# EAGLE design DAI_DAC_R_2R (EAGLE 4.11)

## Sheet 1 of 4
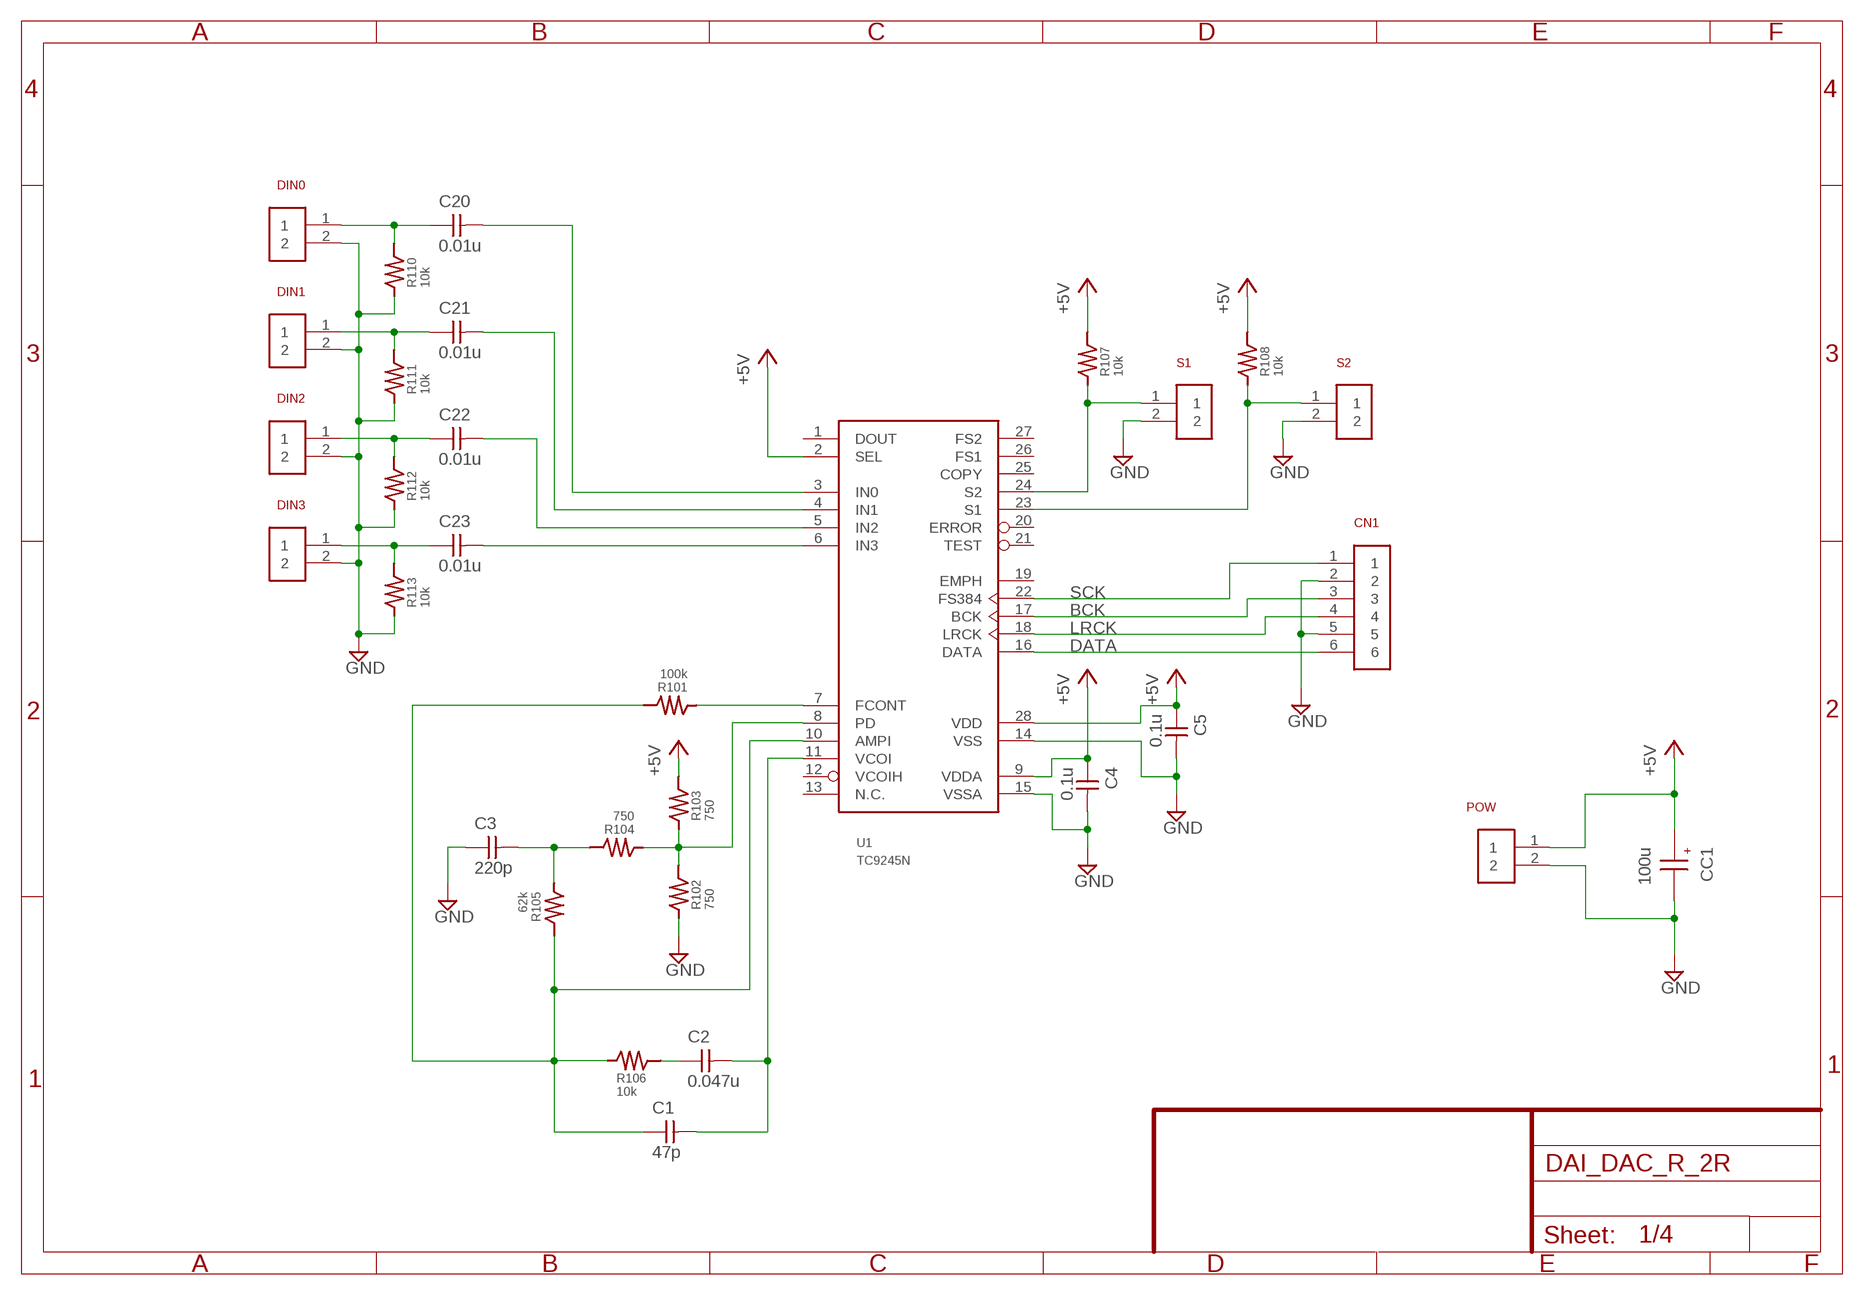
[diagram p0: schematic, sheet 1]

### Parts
C1  47p  CAPNP-5  [C-5]
C2  0.047u  CAPNP-5  [C-5]
C3  220p  CAPNP-5  [C-5]
C4  0.1u  CAPNP-5  [C-5]
C5  0.1u  CAPNP-5  [C-5]
C20  0.01u  CAPNP-5  [C-5]
C21  0.01u  CAPNP-5  [C-5]
C22  0.01u  CAPNP-5  [C-5]
C23  0.01u  CAPNP-5  [C-5]
CC1  100u  CC2.5  [CC2.5]
CN1  PINHEDER_1X6  [PINHEADER_1X6]
DIN0  PINHEADER_1X2  [PINHEADER_1X2]
DIN1  PINHEADER_1X2  [PINHEADER_1X2]
DIN2  PINHEADER_1X2  [PINHEADER_1X2]
DIN3  PINHEADER_1X2  [PINHEADER_1X2]
POW  PINHEADER_1X2  [PINHEADER_1X2]
R101  100k  MINI_R  [MINI_R]
R102  750  MINI_R  [MINI_R]
R103  750  MINI_R  [MINI_R]
R104  750  MINI_R  [MINI_R]
R105  62k  MINI_R  [MINI_R]
R106  10k  MINI_R  [MINI_R]
R107  10k  MINI_R  [MINI_R]
R108  10k  MINI_R  [MINI_R]
R110  10k  MINI_R  [MINI_R]
R111  10k  MINI_R  [MINI_R]
R112  10k  MINI_R  [MINI_R]
R113  10k  MINI_R  [MINI_R]
S1  PINHEADER_1X2  [PINHEADER_1X2]
S2  PINHEADER_1X2  [PINHEADER_1X2]
U1  TC9245N  [TC9245N]

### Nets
+5V: C4.1 C5.1 CC1.P$1 POW.1 R103.P$2(-) R107.P$2(-) R108.P$2(-) U1.2(SEL) U1.9(VDDA) U1.28(VDD) ; also sheet 2,3,4
BCK: CN1.3 U1.17(BCK) ; also sheet 2
DATA: CN1.6 U1.16(DATA) ; also sheet 2
GND: C3.1 C4.2 C5.2 CC1.P$2 CN1.2 CN1.5 DIN0.2 DIN1.2 DIN2.2 DIN3.2 POW.2 R102.P$1 R110.P$1 R111.P$1 R112.P$1 R113.P$1 S1.2 S2.2 U1.14(VSS) U1.15(VSSA) ; also sheet 2,3,4
LRCK: CN1.4 U1.18(LRCK) ; also sheet 2
N$1: C20.1 DIN0.1 R110.P$2(-)
N$2: C21.1 DIN1.1 R111.P$2(-)
N$3: C22.1 DIN2.1 R112.P$2(-)
N$4: C23.1 DIN3.1 R113.P$2(-)
N$5: R107.P$1 S1.1 U1.24(S2)
N$6: R108.P$1 S2.1 U1.23(S1)
N$7: R101.P$1 U1.7(FCONT)
N$8: R102.P$2(-) R103.P$1 R104.P$1 U1.8(PD)
N$9: C3.2 R104.P$2(-) R105.P$1
N$10: C2.1 R106.P$2(-)
N$11: C1.2 C2.2 U1.11(VCOI)
N$12: C1.1 R101.P$2(-) R105.P$2(-) R106.P$1 U1.10(AMPI)
N$63: C23.2 U1.6(IN3)
N$82: C22.2 U1.5(IN2)
N$83: C21.2 U1.4(IN1)
N$84: C20.2 U1.3(IN0)
SCK: CN1.1 U1.22(FS384)
Unconnected: U1.1(DOUT) U1.12(VCOIH) U1.13(N.C.) U1.19(EMPH) U1.20(ERROR) U1.21(TEST) U1.25(COPY) U1.26(FS1) U1.27(FS2)

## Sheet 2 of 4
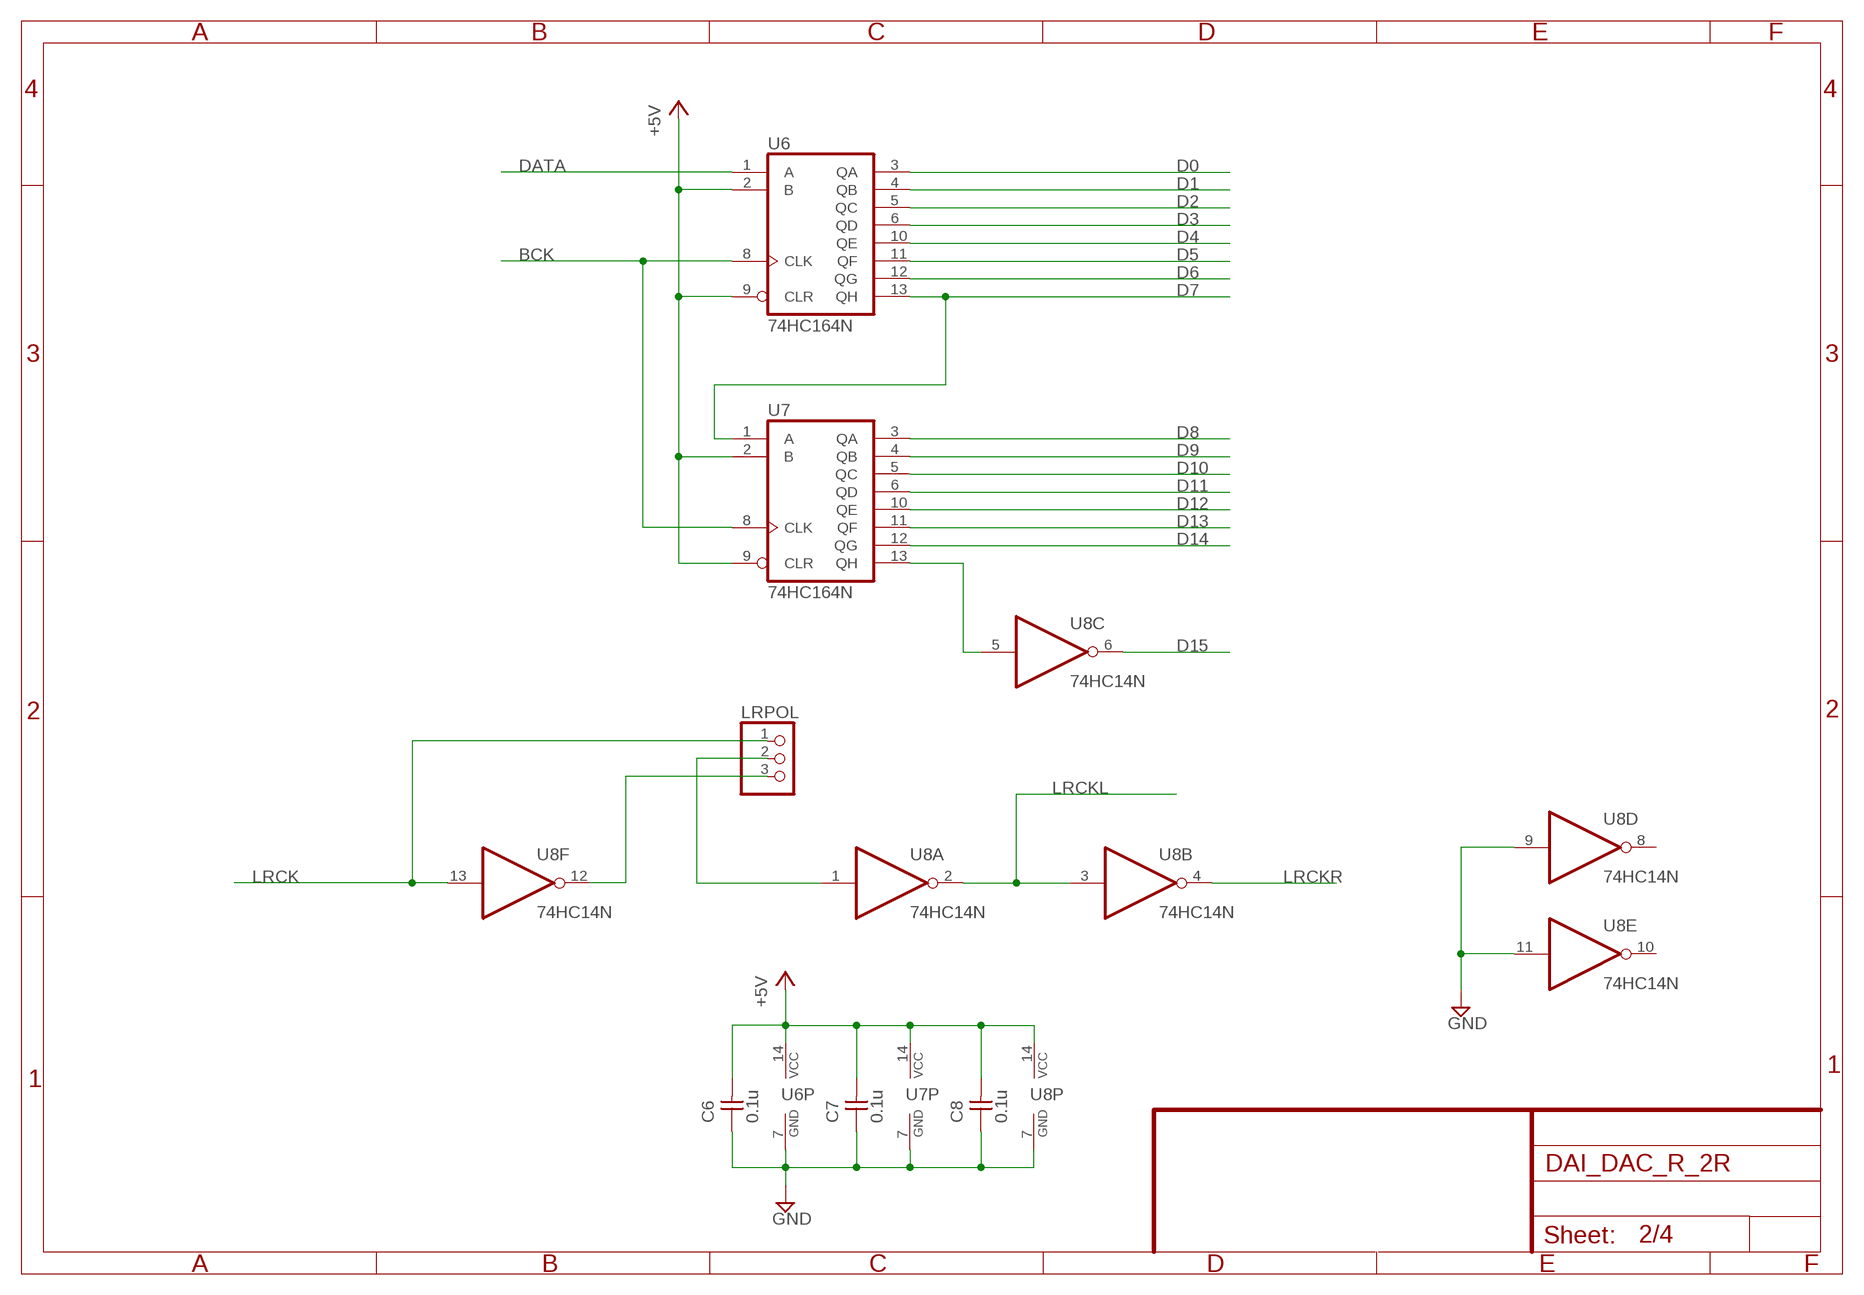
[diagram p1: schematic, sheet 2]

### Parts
C6  0.1u  CAPNP-5  [C-5]
C7  0.1u  CAPNP-5  [C-5]
C8  0.1u  CAPNP-5  [C-5]
LRPOL  PINHEADER_1X3  [1X03]
U6  74HC164N  [DIL14]
U7  74HC164N  [DIL14]
U8  74HC14N  [DIL14]

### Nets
+5V: C6.2 C7.2 C8.2 U6.2(B) U6.9(CLR) U6.14(VCC) U7.2(B) U7.9(CLR) U7.14(VCC) U8.14(P:VCC) ; also sheet 1,3,4
BCK: U6.8(CLK) U7.8(CLK) ; also sheet 1
D0: U6.3(QA) ; also sheet 3,4
D1: U6.4(QB) ; also sheet 3,4
D2: U6.5(QC) ; also sheet 3,4
D3: U6.6(QD) ; also sheet 3,4
D4: U6.10(QE) ; also sheet 3,4
D5: U6.11(QF) ; also sheet 3,4
D6: U6.12(QG) ; also sheet 3,4
D7: U6.13(QH) U7.1(A) ; also sheet 3,4
D8: U7.3(QA) ; also sheet 3,4
D9: U7.4(QB) ; also sheet 3,4
D10: U7.5(QC) ; also sheet 3,4
D11: U7.6(QD) ; also sheet 3,4
D12: U7.10(QE) ; also sheet 3,4
D13: U7.11(QF) ; also sheet 3,4
D14: U7.12(QG) ; also sheet 3,4
D15: U8.6(C:O) ; also sheet 3,4
DATA: U6.1(A) ; also sheet 1
GND: C6.1 C7.1 C8.1 U6.7(GND) U7.7(GND) U8.7(P:GND) U8.9(D:I) U8.11(E:I) ; also sheet 1,3,4
LRCK: LRPOL.1 U8.13(F:I) ; also sheet 1
LRCKL: U8.2(A:O) U8.3(B:I) ; also sheet 3
LRCKR: U8.4(B:O) ; also sheet 4
N$17: U7.13(QH) U8.5(C:I)
N$80: LRPOL.2 U8.1(A:I)
N$81: LRPOL.3 U8.12(F:O)
Unconnected: U8.8(D:O) U8.10(E:O)

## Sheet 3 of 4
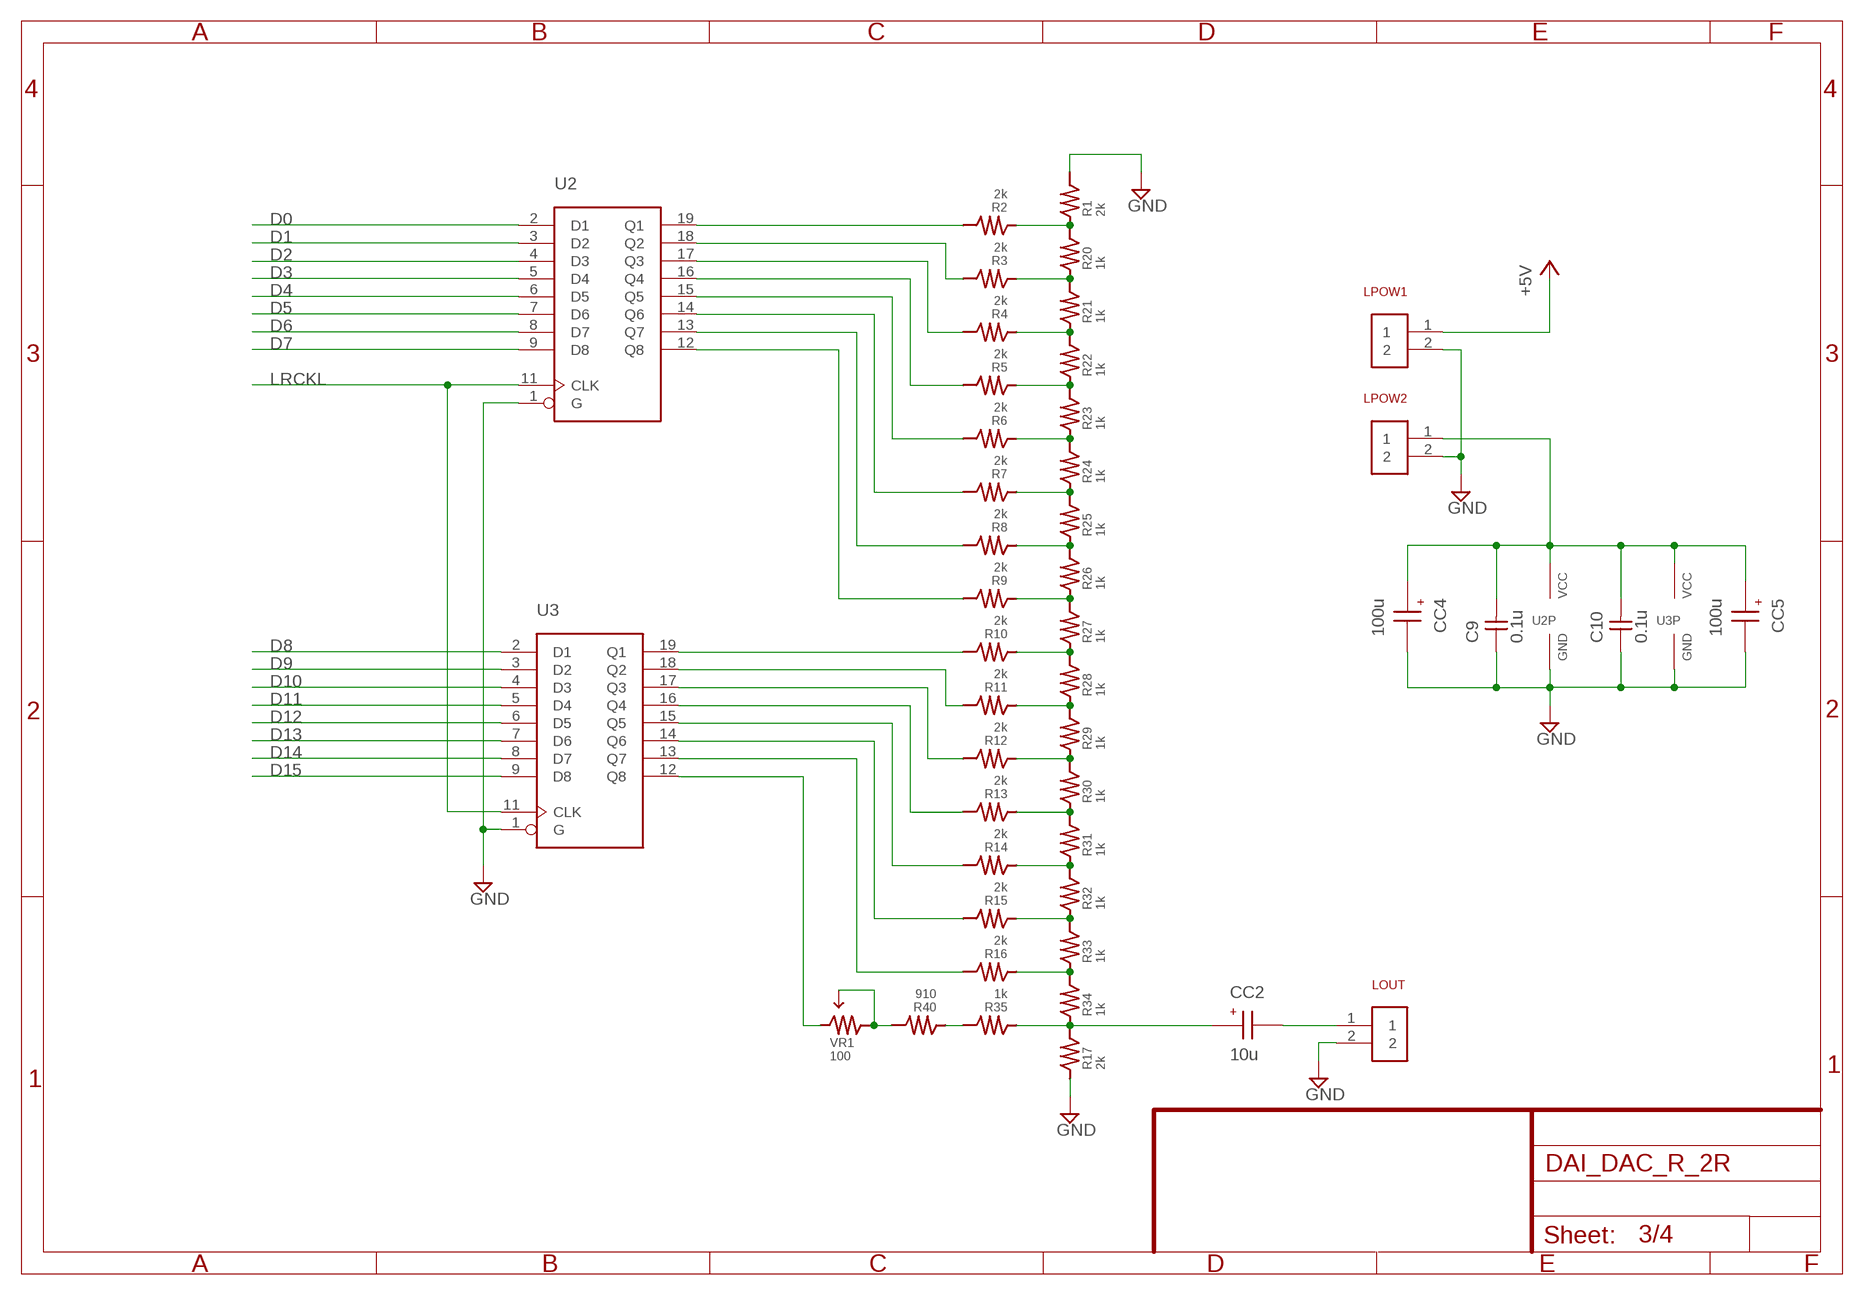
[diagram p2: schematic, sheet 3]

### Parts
C9  0.1u  CAPNP-5  [C-5]
C10  0.1u  CAPNP-5  [C-5]
CC2  10u  CC2.5  [CC2.5]
CC4  100u  CC2.5  [CC2.5]
CC5  100u  CC2.5  [CC2.5]
LOUT  PINHEADER_1X2  [PINHEADER_1X2]
LPOW1  PINHEADER_1X2  [PINHEADER_1X2]
LPOW2  PINHEADER_1X2  [PINHEADER_1X2]
R1  2k  MINI_R  [MINI_R]
R2  2k  MINI_R  [MINI_R]
R3  2k  MINI_R  [MINI_R]
R4  2k  MINI_R  [MINI_R]
R5  2k  MINI_R  [MINI_R]
R6  2k  MINI_R  [MINI_R]
R7  2k  MINI_R  [MINI_R]
R8  2k  MINI_R  [MINI_R]
R9  2k  MINI_R  [MINI_R]
R10  2k  MINI_R  [MINI_R]
R11  2k  MINI_R  [MINI_R]
R12  2k  MINI_R  [MINI_R]
R13  2k  MINI_R  [MINI_R]
R14  2k  MINI_R  [MINI_R]
R15  2k  MINI_R  [MINI_R]
R16  2k  MINI_R  [MINI_R]
R17  2k  MINI_R  [MINI_R]
R20  1k  MINI_R  [MINI_R]
R21  1k  MINI_R  [MINI_R]
R22  1k  MINI_R  [MINI_R]
R23  1k  MINI_R  [MINI_R]
R24  1k  MINI_R  [MINI_R]
R25  1k  MINI_R  [MINI_R]
R26  1k  MINI_R  [MINI_R]
R27  1k  MINI_R  [MINI_R]
R28  1k  MINI_R  [MINI_R]
R29  1k  MINI_R  [MINI_R]
R30  1k  MINI_R  [MINI_R]
R31  1k  MINI_R  [MINI_R]
R32  1k  MINI_R  [MINI_R]
R33  1k  MINI_R  [MINI_R]
R34  1k  MINI_R  [MINI_R]
R35  1k  MINI_R  [MINI_R]
R40  910  MINI_R  [MINI_R]
U2  74HC574  [DIL20]
U3  74HC574  [DIL20]
VR1  100  VR  [VR]

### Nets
+5V: LPOW1.1 ; also sheet 1,2,4
D0: U2.2(D1) ; also sheet 2,4
D1: U2.3(D2) ; also sheet 2,4
D2: U2.4(D3) ; also sheet 2,4
D3: U2.5(D4) ; also sheet 2,4
D4: U2.6(D5) ; also sheet 2,4
D5: U2.7(D6) ; also sheet 2,4
D6: U2.8(D7) ; also sheet 2,4
D7: U2.9(D8) ; also sheet 2,4
D8: U3.2(D1) ; also sheet 2,4
D9: U3.3(D2) ; also sheet 2,4
D10: U3.4(D3) ; also sheet 2,4
D11: U3.5(D4) ; also sheet 2,4
D12: U3.6(D5) ; also sheet 2,4
D13: U3.7(D6) ; also sheet 2,4
D14: U3.8(D7) ; also sheet 2,4
D15: U3.9(D8) ; also sheet 2,4
GND: C9.1 C10.1 CC4.P$2 CC5.P$2 LOUT.2 LPOW1.2 LPOW2.2 R1.P$2(-) R17.P$1 U2.1(G) U2.10(GND) U3.1(G) U3.10(GND) ; also sheet 1,2,4
LRCKL: U2.11(CLK) U3.11(CLK) ; also sheet 2
N$13: U3.12(Q8) VR1.1
N$14: R3.P$1 R20.P$1 R21.P$2(-)
N$15: R4.P$1 R21.P$1 R22.P$2(-)
N$16: R5.P$1 R22.P$1 R23.P$2(-)
N$18: R6.P$1 R23.P$1 R24.P$2(-)
N$19: R7.P$1 R24.P$1 R25.P$2(-)
N$20: R8.P$1 R25.P$1 R26.P$2(-)
N$21: R9.P$1 R26.P$1 R27.P$2(-)
N$22: R10.P$1 R27.P$1 R28.P$2(-)
N$23: R11.P$1 R28.P$1 R29.P$2(-)
N$24: R12.P$1 R29.P$1 R30.P$2(-)
N$25: R13.P$1 R30.P$1 R31.P$2(-)
N$26: R14.P$1 R31.P$1 R32.P$2(-)
N$27: R15.P$1 R32.P$1 R33.P$2(-)
N$28: R16.P$1 R33.P$1 R34.P$2(-)
N$30: R1.P$1 R2.P$1 R20.P$2(-)
N$32: R40.P$2(-) VR1.2 VR1.3
N$33: R35.P$2(-) R40.P$1
N$34: R2.P$2(-) U2.19(Q1)
N$35: R3.P$2(-) U2.18(Q2)
N$36: R4.P$2(-) U2.17(Q3)
N$37: R5.P$2(-) U2.16(Q4)
N$38: R6.P$2(-) U2.15(Q5)
N$39: R7.P$2(-) U2.14(Q6)
N$40: R8.P$2(-) U2.13(Q7)
N$41: R9.P$2(-) U2.12(Q8)
N$42: R10.P$2(-) U3.19(Q1)
N$43: R11.P$2(-) U3.18(Q2)
N$44: R12.P$2(-) U3.17(Q3)
N$45: R13.P$2(-) U3.16(Q4)
N$46: R14.P$2(-) U3.15(Q5)
N$47: R15.P$2(-) U3.14(Q6)
N$48: R16.P$2(-) U3.13(Q7)
N$85: C9.2 C10.2 CC4.P$1 CC5.P$1 LPOW2.1 U2.20(VCC) U3.20(VCC)
OUT_L: CC2.P$1 R17.P$2(-) R34.P$1 R35.P$1
OUT_LL: CC2.P$2 LOUT.1

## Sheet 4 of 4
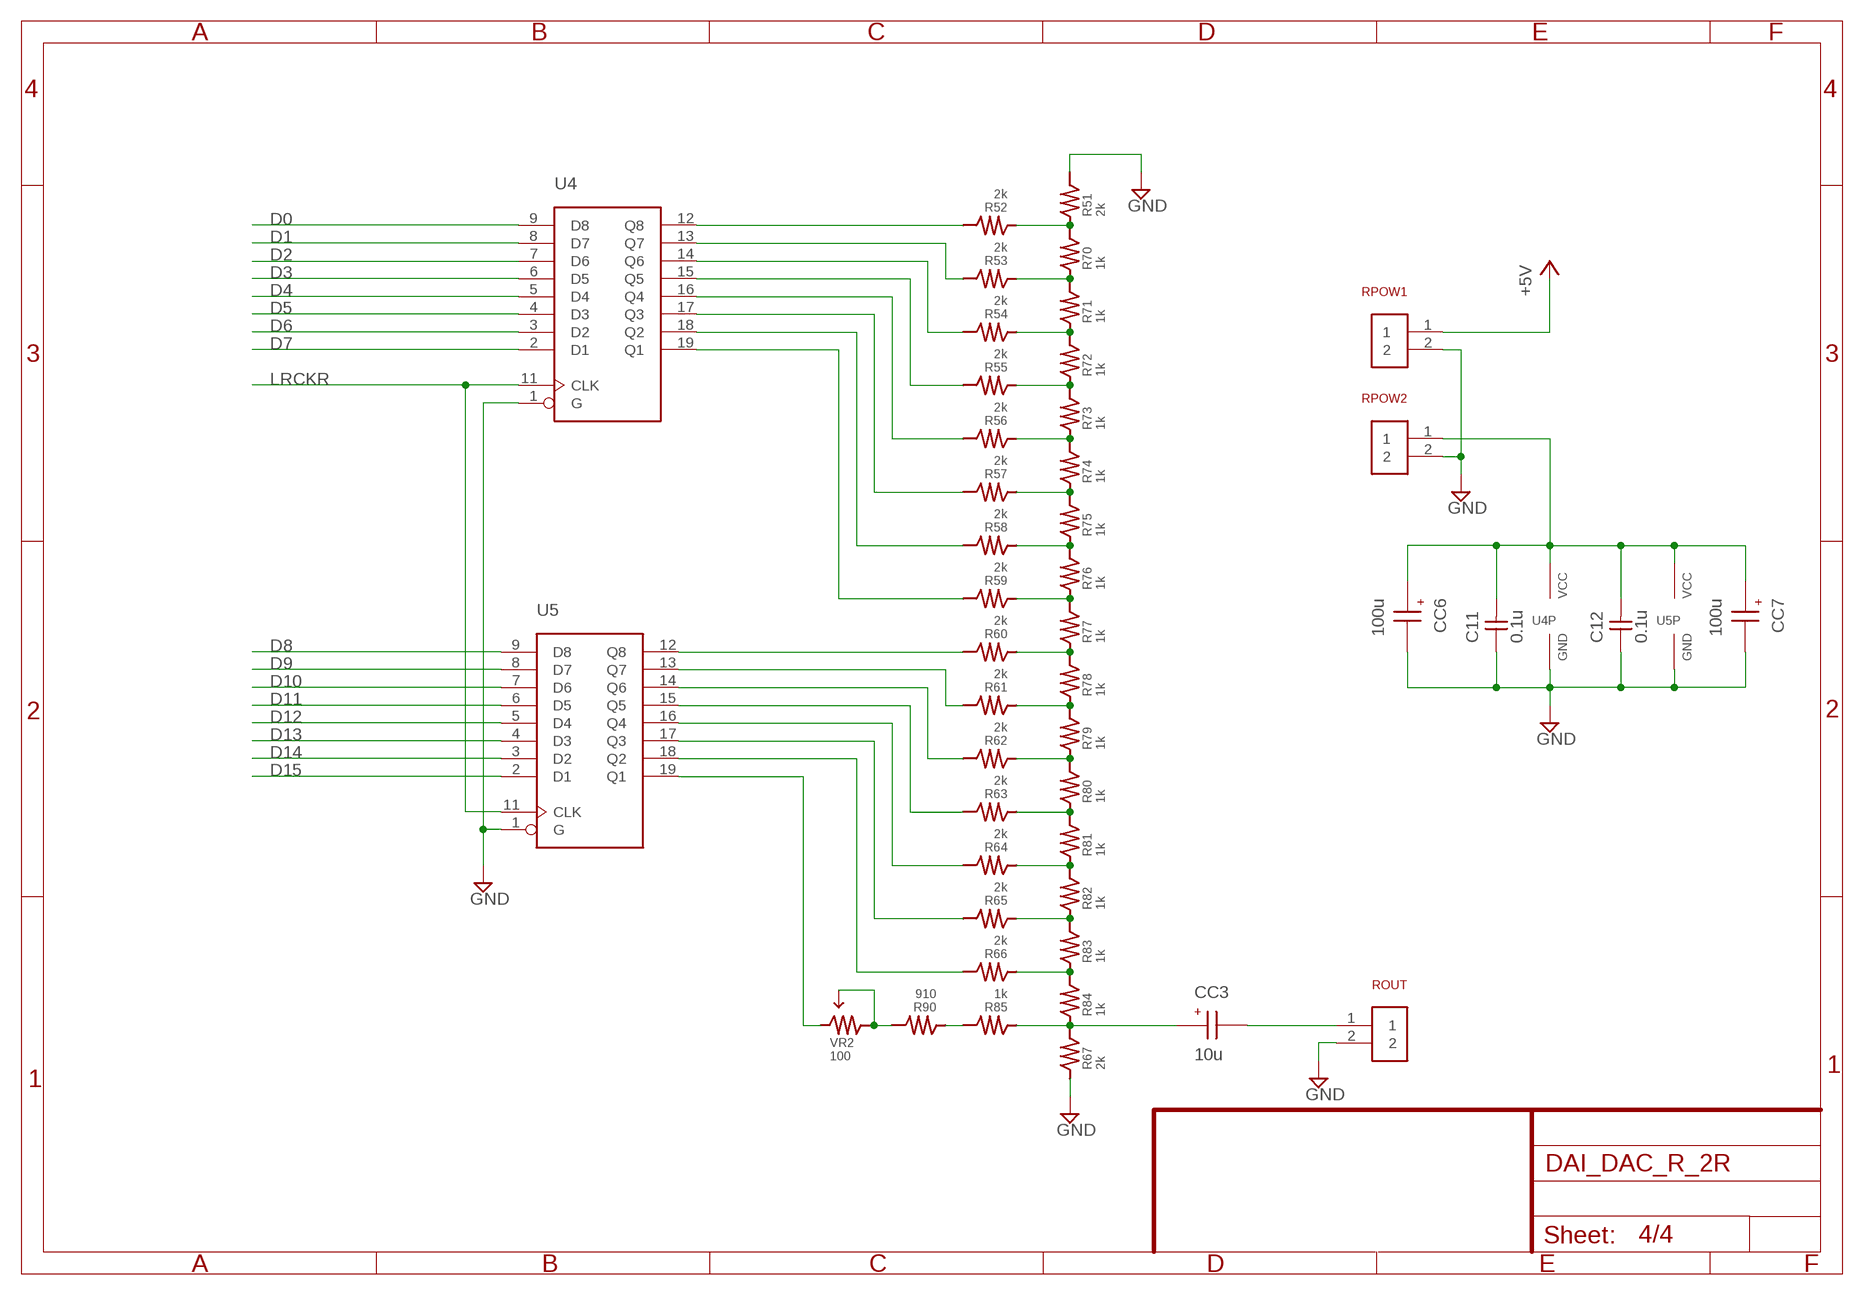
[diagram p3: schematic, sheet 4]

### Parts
C11  0.1u  CAPNP-5  [C-5]
C12  0.1u  CAPNP-5  [C-5]
CC3  10u  CC2.5  [CC2.5]
CC6  100u  CC2.5  [CC2.5]
CC7  100u  CC2.5  [CC2.5]
R51  2k  MINI_R  [MINI_R]
R52  2k  MINI_R  [MINI_R]
R53  2k  MINI_R  [MINI_R]
R54  2k  MINI_R  [MINI_R]
R55  2k  MINI_R  [MINI_R]
R56  2k  MINI_R  [MINI_R]
R57  2k  MINI_R  [MINI_R]
R58  2k  MINI_R  [MINI_R]
R59  2k  MINI_R  [MINI_R]
R60  2k  MINI_R  [MINI_R]
R61  2k  MINI_R  [MINI_R]
R62  2k  MINI_R  [MINI_R]
R63  2k  MINI_R  [MINI_R]
R64  2k  MINI_R  [MINI_R]
R65  2k  MINI_R  [MINI_R]
R66  2k  MINI_R  [MINI_R]
R67  2k  MINI_R  [MINI_R]
R70  1k  MINI_R  [MINI_R]
R71  1k  MINI_R  [MINI_R]
R72  1k  MINI_R  [MINI_R]
R73  1k  MINI_R  [MINI_R]
R74  1k  MINI_R  [MINI_R]
R75  1k  MINI_R  [MINI_R]
R76  1k  MINI_R  [MINI_R]
R77  1k  MINI_R  [MINI_R]
R78  1k  MINI_R  [MINI_R]
R79  1k  MINI_R  [MINI_R]
R80  1k  MINI_R  [MINI_R]
R81  1k  MINI_R  [MINI_R]
R82  1k  MINI_R  [MINI_R]
R83  1k  MINI_R  [MINI_R]
R84  1k  MINI_R  [MINI_R]
R85  1k  MINI_R  [MINI_R]
R90  910  MINI_R  [MINI_R]
ROUT  PINHEADER_1X2  [PINHEADER_1X2]
RPOW1  PINHEADER_1X2  [PINHEADER_1X2]
RPOW2  PINHEADER_1X2  [PINHEADER_1X2]
U4  74HC574R  [DIL20]
U5  74HC574R  [DIL20]
VR2  100  VR  [VR]

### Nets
$N70: R58.P$2(-) U4.18(Q2)
+5V: RPOW1.1 ; also sheet 1,2,3
D0: U4.9(D8) ; also sheet 2,3
D1: U4.8(D7) ; also sheet 2,3
D2: U4.7(D6) ; also sheet 2,3
D3: U4.6(D5) ; also sheet 2,3
D4: U4.5(D4) ; also sheet 2,3
D5: U4.4(D3) ; also sheet 2,3
D6: U4.3(D2) ; also sheet 2,3
D7: U4.2(D1) ; also sheet 2,3
D8: U5.9(D8) ; also sheet 2,3
D9: U5.8(D7) ; also sheet 2,3
D10: U5.7(D6) ; also sheet 2,3
D11: U5.6(D5) ; also sheet 2,3
D12: U5.5(D4) ; also sheet 2,3
D13: U5.4(D3) ; also sheet 2,3
D14: U5.3(D2) ; also sheet 2,3
D15: U5.2(D1) ; also sheet 2,3
GND: C11.1 C12.1 CC6.P$2 CC7.P$2 R51.P$2(-) R67.P$1 ROUT.2 RPOW1.2 RPOW2.2 U4.1(G) U4.10(GND) U5.1(G) U5.10(GND) ; also sheet 1,2,3
LRCKR: U4.11(CLK) U5.11(CLK) ; also sheet 2
N$29: R53.P$1 R70.P$1 R71.P$2(-)
N$31: R54.P$1 R71.P$1 R72.P$2(-)
N$49: R55.P$1 R72.P$1 R73.P$2(-)
N$50: R56.P$1 R73.P$1 R74.P$2(-)
N$51: R57.P$1 R74.P$1 R75.P$2(-)
N$52: R58.P$1 R75.P$1 R76.P$2(-)
N$53: R59.P$1 R76.P$1 R77.P$2(-)
N$54: R60.P$1 R77.P$1 R78.P$2(-)
N$55: R61.P$1 R78.P$1 R79.P$2(-)
N$56: R62.P$1 R79.P$1 R80.P$2(-)
N$57: R63.P$1 R80.P$1 R81.P$2(-)
N$58: R64.P$1 R81.P$1 R82.P$2(-)
N$59: R65.P$1 R82.P$1 R83.P$2(-)
N$60: R66.P$1 R83.P$1 R84.P$2(-)
N$61: R51.P$1 R52.P$1 R70.P$2(-)
N$62: R85.P$2(-) R90.P$1
N$64: R52.P$2(-) U4.12(Q8)
N$65: R53.P$2(-) U4.13(Q7)
N$66: R54.P$2(-) U4.14(Q6)
N$67: R55.P$2(-) U4.15(Q5)
N$68: R56.P$2(-) U4.16(Q4)
N$69: R57.P$2(-) U4.17(Q3)
N$70: R90.P$2(-) VR2.2 VR2.3
N$71: R59.P$2(-) U4.19(Q1)
N$72: R60.P$2(-) U5.12(Q8)
N$73: R61.P$2(-) U5.13(Q7)
N$74: R62.P$2(-) U5.14(Q6)
N$75: R63.P$2(-) U5.15(Q5)
N$76: R64.P$2(-) U5.16(Q4)
N$77: R65.P$2(-) U5.17(Q3)
N$78: R66.P$2(-) U5.18(Q2)
N$79: U5.19(Q1) VR2.1
N$86: C11.2 C12.2 CC6.P$1 CC7.P$1 RPOW2.1 U4.20(VCC) U5.20(VCC)
OUT_R: CC3.P$1 R67.P$2(-) R84.P$1 R85.P$1
OUT_RR: CC3.P$2 ROUT.1

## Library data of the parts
C1-C12 C20-C23 = DAI_FIFO_R_2R:CAPNP-5
CC1-CC7 = DAI_FIFO_R_2R:CC2.5
CN1 = DAI_FIFO_R_2R:PINHEDER_1X6
DIN0 DIN1-DIN3 LOUT LPOW1 LPOW2 POW ROUT RPOW1 RPOW2 S1 S2 = DAI_FIFO_R_2R:PINHEADER_1X2
LRPOL = DAI_FIFO_R_2R:PINHEADER_1X3: PIN HEADER
R1-R17 R20-R35 R40 R51-R67 R70-R85 R90 R101-R108 R110-R113 = DAI_FIFO_R_2R:MINI_R
U1 = DAI_FIFO_R_2R:TC9245N
U2 U3 = DAI_FIFO_R_2R:74HC574
U4 U5 = DAI_FIFO_R_2R:74HC574R
U6 U7 = DAI_FIFO_R_2R:74*164: 8-bit parallel out SHIFT REGISTER
U8 = DAI_FIFO_R_2R:74*14: Hex INVERTER
VR1 VR2 = DAI_FIFO_R_2R:VR

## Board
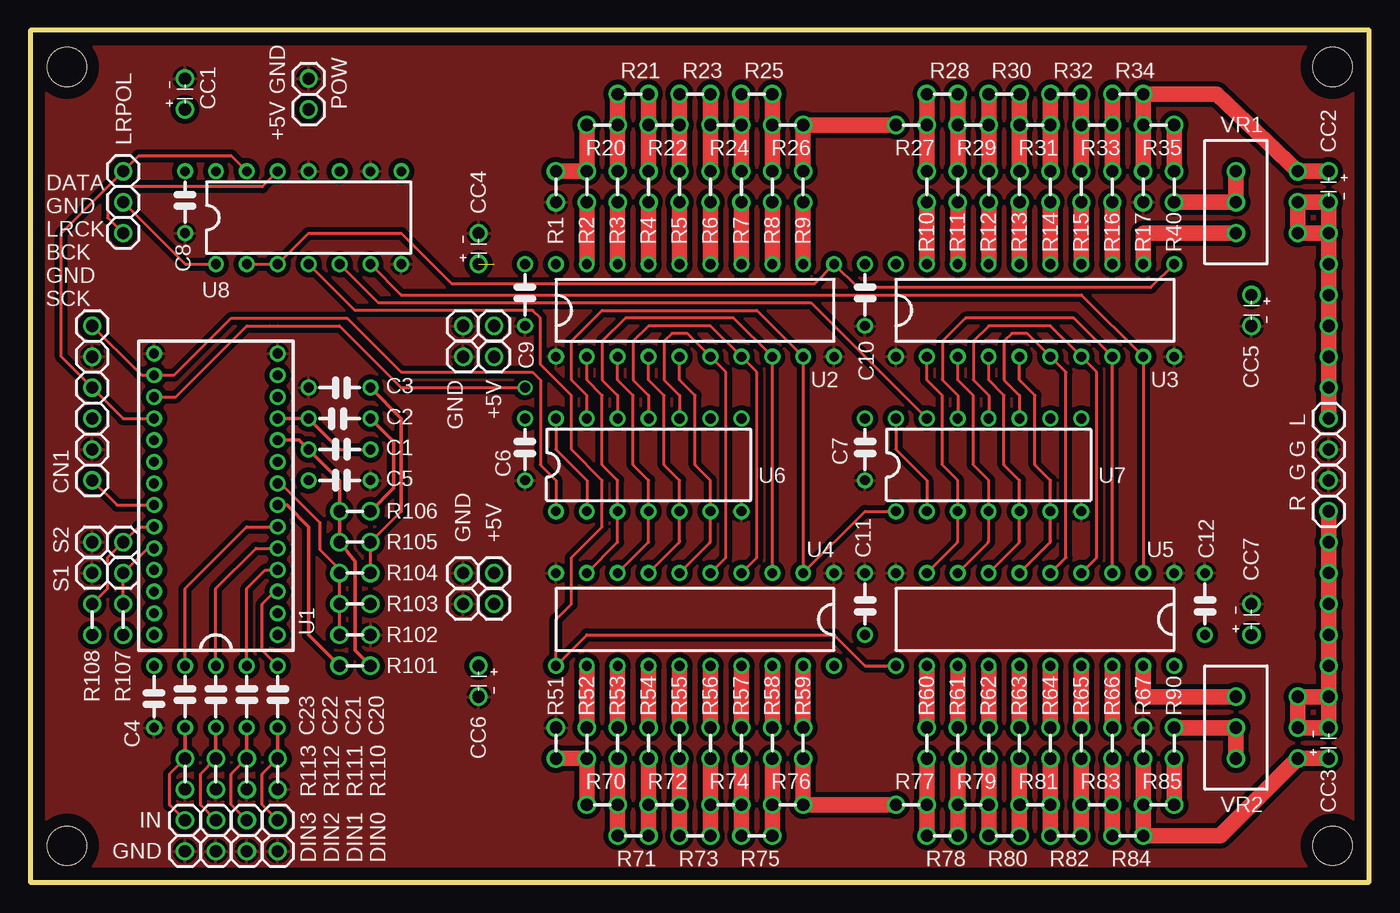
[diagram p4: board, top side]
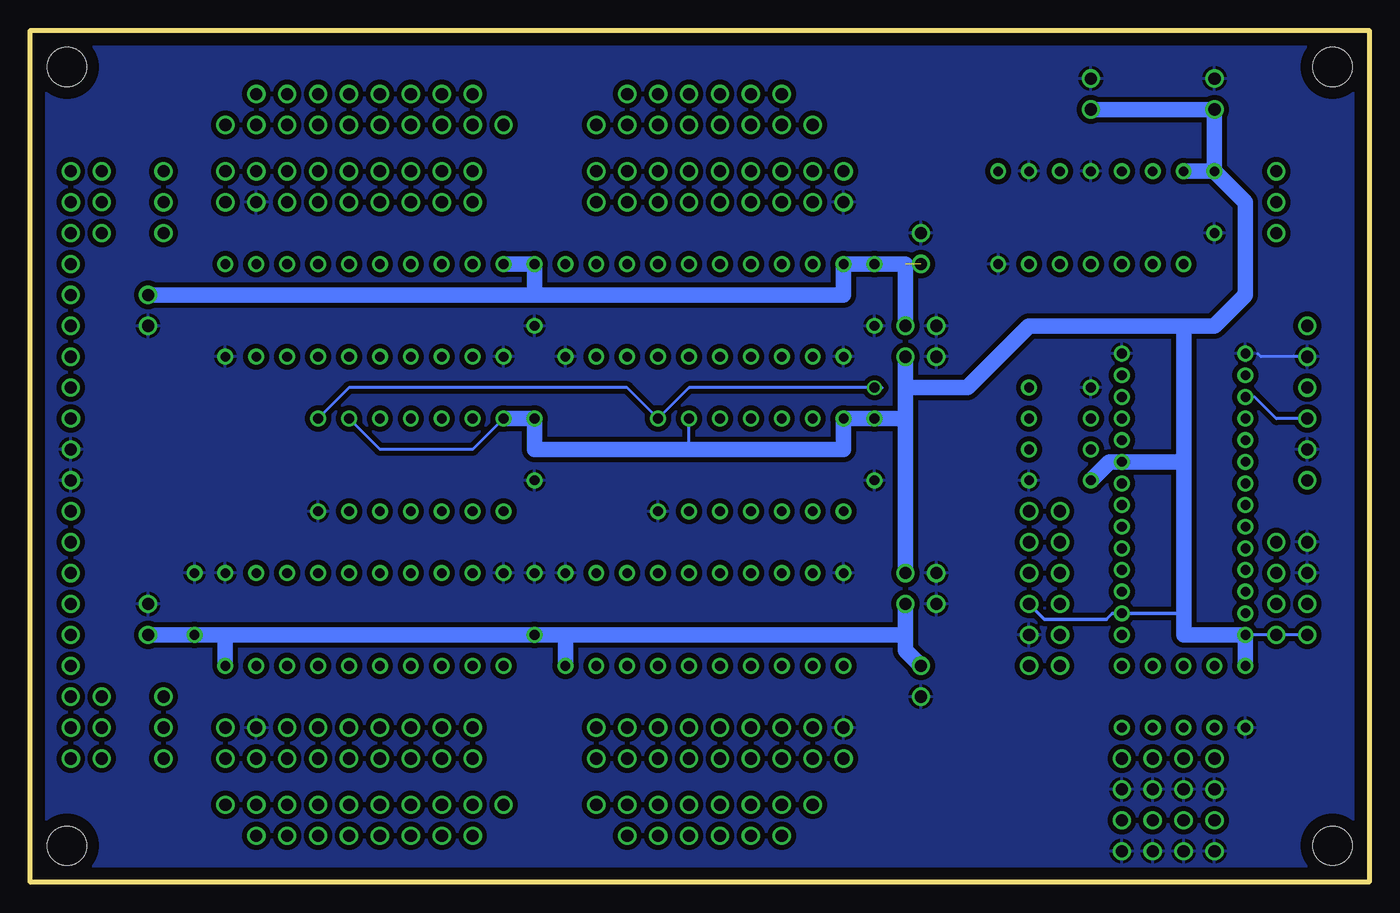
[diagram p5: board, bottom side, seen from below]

Size 110 x 70 mm. Coordinates in mm from the lower left corner, seen from the top.
Outline: 0,0 110,0 110,70 0,70 0,0
Copper layers (1*16): Top 0.035mm / dielectric 1.5mm / Bottom 0.035mm
Design rules "8mils": minimum track width 10mil, minimum drill 24mil, track to track 8mil, track to pad 8mil, pad to pad 8mil, via to via 8mil, smd to smd 8mil, copper to edge 40mil, drill to drill 10mil, minimum pad ring 10mil, minimum via ring 8mil, stop-mask expansion 0mil, vias tented up to drill 0mil, thermal gap 10mil
Holes 3.2 mm at 3,3 3,67 107,67 107,3

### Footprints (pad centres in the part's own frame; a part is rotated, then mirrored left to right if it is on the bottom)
C-5 = drill 0.8 round: 1 -2.54,0; 2 2.54,0
CC2.5 = drill 1 round: P$1 0,0; P$2 2.54,0
PINHEADER_1X6 = drill 1 round: 1 -7.62,0; 2 -5.08,0; 3 -2.54,0; 4 0,0; 5 2.54,0; 6 5.08,0
PINHEADER_1X2 = drill 1 round: 1 -2.54,0; 2 0,0
1X03 = drill 1 round: 1 -2.54,0; 2 0,0; 3 2.54,0
MINI_R = drill 1 round: P$1 -1.27,0; P$2 1.27,0
TC9245N = drill 0.8 pad 1.27 round: 1 0,0; 2 1.778,0; 3 3.556,0; 4 5.334,0; 5 7.112,0; 6 8.89,0; 7 10.668,0; 8 12.446,0; 9 14.224,0; 10 16.002,0; 11 17.78,0; 12 19.558,0; 13 21.336,0; 14 23.114,0; 15 23.114,10.16; 16 21.336,10.16; 17 19.558,10.16; 18 17.78,10.16; 19 16.002,10.16; 20 14.224,10.16; 21 12.446,10.16; 22 10.668,10.16; 23 8.89,10.16; 24 7.112,10.16; 25 5.334,10.16; 26 3.556,10.16; 27 1.778,10.16; 28 0,10.16
DIL20 = drill 0.8 round: 1 -10.16,-2.54; 2 -7.62,-2.54; 3 -5.08,-2.54; 4 -2.54,-2.54; 5 0,-2.54; 6 2.54,-2.54; 7 5.08,-2.54; 8 7.62,-2.54; 9 10.16,-2.54; 10 12.7,-2.54; 11 12.7,5.08; 12 10.16,5.08; 13 7.62,5.08; 14 5.08,5.08; 15 2.54,5.08; 16 0,5.08; 17 -2.54,5.08; 18 -5.08,5.08; 19 -7.62,5.08; 20 -10.16,5.08
DIL14 = drill 0.8 round: 1 -7.62,-3.81; 2 -5.08,-3.81; 3 -2.54,-3.81; 4 0,-3.81; 5 2.54,-3.81; 6 5.08,-3.81; 7 7.62,-3.81; 8 7.62,3.81; 9 5.08,3.81; 10 2.54,3.81; 11 0,3.81; 12 -2.54,3.81; 13 -5.08,3.81; 14 -7.62,3.81
VR = drill 1 round: 1 -2.54,0; 2 0,0; 3 2.54,0

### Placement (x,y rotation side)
C1  25.4,35.56 0 top
C2  25.4,38.1 180 top
C3  25.4,40.64 0 top
C4  10.16,15.24 270 top
C5  25.4,33.02 0 top
C6  40.64,35.56 90 top
C7  68.58,35.56 90 top
C8  12.7,55.88 90 top
C9  40.64,48.26 90 top
C10  68.58,48.26 90 top
C11  68.58,22.86 270 top
C12  96.52,22.86 270 top
C20  20.32,15.24 90 top
C21  17.78,15.24 90 top
C22  15.24,15.24 90 top
C23  12.7,15.24 90 top
CC1  12.7,63.5 90 top
CC2  106.68,58.42 270 top
CC3  106.68,10.16 90 top
CC4  36.83,50.8 90 top
CC5  100.33,48.26 270 top
CC6  36.83,17.78 270 top
CC7  100.33,20.32 90 top
CN1  5.08,40.64 90 top
DIN0  20.32,2.54 270 top
DIN1  17.78,2.54 270 top
DIN2  15.24,2.54 270 top
DIN3  12.7,2.54 270 top
LOUT  106.68,35.56 270 top
LPOW1  35.56,43.18 180 top
LPOW2  35.56,45.72 180 top
LRPOL  7.62,55.88 270 top
POW  22.86,66.04 90 top
R1  43.18,57.15 270 top
R2  45.72,57.15 270 top
R3  48.26,57.15 270 top
R4  50.8,57.15 270 top
R5  53.34,57.15 270 top
R6  55.88,57.15 270 top
R7  58.42,57.15 270 top
R8  60.96,57.15 270 top
R9  63.5,57.15 270 top
R10  73.66,57.15 270 top
R11  76.2,57.15 270 top
R12  78.74,57.15 270 top
R13  81.28,57.15 270 top
R14  83.82,57.15 270 top
R15  86.36,57.15 270 top
R16  88.9,57.15 270 top
R17  91.44,57.15 90 top
R20  46.99,62.23 180 top
R21  49.53,64.77 180 top
R22  52.07,62.23 180 top
R23  54.61,64.77 180 top
R24  57.15,62.23 180 top
R25  59.69,64.77 180 top
R26  62.23,62.23 180 top
R27  72.39,62.23 180 top
R28  74.93,64.77 180 top
R29  77.47,62.23 180 top
R30  80.01,64.77 180 top
R31  82.55,62.23 180 top
R32  85.09,64.77 180 top
R33  87.63,62.23 180 top
R34  90.17,64.77 180 top
R35  92.71,62.23 0 top
R40  93.98,57.15 270 top
R51  43.18,11.43 90 top
R52  45.72,11.43 90 top
R53  48.26,11.43 90 top
R54  50.8,11.43 90 top
R55  53.34,11.43 90 top
R56  55.88,11.43 90 top
R57  58.42,11.43 90 top
R58  60.96,11.43 90 top
R59  63.5,11.43 90 top
R60  73.66,11.43 90 top
R61  76.2,11.43 90 top
R62  78.74,11.43 90 top
R63  81.28,11.43 90 top
R64  83.82,11.43 90 top
R65  86.36,11.43 90 top
R66  88.9,11.43 90 top
R67  91.44,11.43 270 top
R70  46.99,6.35 180 top
R71  49.53,3.81 180 top
R72  52.07,6.35 180 top
R73  54.61,3.81 180 top
R74  57.15,6.35 180 top
R75  59.69,3.81 180 top
R76  62.23,6.35 180 top
R77  72.39,6.35 180 top
R78  74.93,3.81 180 top
R79  77.47,6.35 180 top
R80  80.01,3.81 180 top
R81  82.55,6.35 180 top
R82  85.09,3.81 180 top
R83  87.63,6.35 180 top
R84  90.17,3.81 180 top
R85  92.71,6.35 0 top
R90  93.98,11.43 90 top
R101  26.67,17.78 0 top
R102  26.67,20.32 180 top
R103  26.67,22.86 0 top
R104  26.67,25.4 0 top
R105  26.67,27.94 180 top
R106  26.67,30.48 0 top
R107  7.62,21.59 270 top
R108  5.08,21.59 270 top
R110  20.32,8.89 90 top
R111  17.78,8.89 90 top
R112  15.24,8.89 90 top
R113  12.7,8.89 90 top
ROUT  106.68,33.02 90 top
RPOW1  35.56,25.4 180 top
RPOW2  35.56,22.86 180 top
S1  5.08,25.4 180 top
S2  5.08,27.94 180 top
U1  20.32,20.32 90 top
U2  53.34,45.72 0 top
U3  81.28,45.72 0 top
U4  55.88,22.86 180 top
U5  83.82,22.86 180 top
U6  50.8,34.29 0 top
U7  78.74,34.29 0 top
U8  22.86,54.61 0 top
VR1  99.06,55.88 90 top
VR2  99.06,12.7 270 top

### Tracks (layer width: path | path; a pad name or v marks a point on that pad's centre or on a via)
$N70
  Top 1.27: R58.P$2 U4.18
+5V
  Top 0.254: U6.2 45.72,33.02 43.18,35.56 U6.14 | U7.2 73.66,33.02 71.12,35.56 U7.14
  Bottom 0.254: 55.88,35.56 U6.9 | R108.P$2 R107.P$2 U1.28 | 21.08,22.1 21.59,21.59 | 15.24,21.59 15.75,22.1 | U7.9 81.28,35.56 73.66,35.56 U7.14
  Bottom 0.305: 21.08,22.1 U1.2 15.75,22.1 | 21.59,21.59 26.67,21.59 R103.P$2
  Bottom 1.27: C8.2 U8.14 | U7.14 C7.2 68.58,35.56 55.88,35.56 43.18,35.56 U6.14 C6.2 38.1,38.1 | C8.2 10.16,55.88 10.16,48.26 12.7,45.72 15.24,45.72 | 15.24,34.92 15.24,21.59 15.24,20.32 U1.28 C4.1 | 15.24,34.92 15.24,45.72 | 15.24,34.92 15.62,34.54 U1.9 21.34,34.54 C5.1 | POW.1 CC1.P$1 C8.2 | 15.24,45.72 27.94,45.72 33.02,40.64 38.1,40.64 LPOW1.1 38.1,38.1 | 38.1,38.1 RPOW1.1
BCK  (via drill 0.8)
  Top 0.254: 19.68,45.72 17.78,45.72 11.94,39.88 U1.17 | 19.68,45.72 20.32,45.72 | 19.68,45.72 25.4,45.72 30.48,40.64 v40.64,40.64
  Bottom 0.254: U7.8 83.82,40.64 60.96,40.64 U6.8 55.88,40.64 v40.64,40.64 40.01,40.64 | U1.17 9.4,39.88 7.62,38.1 CN1.3
D0
  Top 0.254: U4.9 48.26,27.94 U6.3 48.26,33.02 46.99,34.29 46.99,40.01 45.72,41.27 U2.2
D1
  Top 0.254: U4.8 50.8,27.94 U6.4 50.8,33.02 49.53,34.29 49.53,40.01 48.26,41.27 U2.3
D2
  Top 0.254: U4.7 53.27,27.87 arc45 53.34,28.05 U6.5 53.34,33.02 52.07,34.29 52.07,40.01 50.8,41.27 U2.4
D3
  Top 0.254: U4.6 55.81,27.87 arc45 55.88,28.05 U6.6 55.88,33.02 54.61,34.29 54.61,40.01 53.34,41.27 U2.5
D4
  Top 0.254: U4.5 57.15,26.67 57.15,41.91 U2.6 53.98,45.09 52.7,45.09 52.07,44.45 52.07,41.27 53.34,40.01 U6.10
D5
  Top 0.254: U4.4 59.69,26.67 59.69,41.91 U2.7 55.88,45.72 50.8,45.72 49.53,44.45 49.53,41.27 50.8,40.01 U6.11
D6
  Top 0.254: U4.3 U2.8 57.78,46.35 48.9,46.35 46.99,44.45 46.99,41.27 48.26,40.01 U6.12
D7
  Top 0.254: U7.1 68.58,30.48 U4.2 U2.9 59.69,46.99 46.99,46.99 44.45,44.45 44.45,41.27 45.72,40.01 U6.13
D8
  Top 0.254: U5.9 76.13,27.87 arc45 76.2,28.05 U7.3 76.2,33.02 74.93,34.29 74.93,40.01 73.66,41.27 U3.2
D9
  Top 0.254: U5.8 78.67,27.87 arc45 78.74,28.05 U7.4 78.74,33.02 77.47,34.29 77.47,40.01 76.2,41.27 U3.3
D10
  Top 0.254: U5.7 81.21,27.87 arc45 81.28,28.05 U7.5 81.28,33.02 80.01,34.29 80.01,40.01 78.74,41.27 U3.4
D11
  Top 0.254: U5.6 83.75,27.87 arc45 83.82,28.05 U7.6 83.82,33.02 82.55,34.29 82.55,40.01 81.28,41.27 U3.5
D12
  Top 0.254: U5.5 85.09,26.67 85.09,41.91 U3.6 81.92,45.09 80.64,45.09 80.01,44.45 80.01,41.27 81.28,40.01 U7.10
D13
  Top 0.254: U5.4 87.63,26.67 87.63,41.91 U3.7 83.82,45.72 78.74,45.72 77.47,44.45 77.47,41.27 78.74,40.01 U7.11
D14
  Top 0.254: U5.3 U3.8 85.72,46.35 76.83,46.35 74.93,44.45 74.93,41.27 76.2,40.01 U7.12
D15
  Top 0.254: U5.2 U3.9 86.36,48.26 30.48,48.26 U8.6
DATA
  Top 0.254: 8.89,41.91 9.03,41.77 | 8.89,41.91 CN1.6 | 8.89,41.91 9.14,41.66 U1.16 11.81,41.66 16.51,46.35 26.04,46.35 30.48,41.91 41.27,41.91 41.91,41.27 41.91,34.29 43.18,33.02 U6.1
GND
  Bottom 0.254: 9.14,43.43 8.89,43.18 CN1.5
  pour Top (isolate 0.406): 0,69.14 109.69,69.14 109.69,0 0,0
  pour Bottom (isolate 0.406): 0,69.14 109.69,69.14 109.69,0 0,0
LRCK
  Top 0.254: U1.18 7.62,38.1 CN1.4 2.54,43.18 2.54,53.34 LRPOL.1 8.89,59.69 16.51,59.69 U8.13
LRCKL
  Top 0.254: U8.2 U8.3 22.86,53.34 30.48,53.34 34.61,49.21 64.45,49.21 U2.11 67.94,48.9 92.08,48.9 U3.11
LRCKR
  Top 0.254: U5.11 68.58,17.78 66.04,20.32 45.72,20.32 U4.11 43.18,21.59 44.45,22.86 44.45,26.67 46.99,29.21 46.99,33.02 44.45,35.56 44.45,40.01 41.91,42.55 41.91,46.35 41.27,46.99 26.67,46.99 U8.4
N$1
  Top 0.254: DIN0.1 19.05,6.35 19.05,8.89 R110.P$2
  Top 0.305: R110.P$2 C20.1
N$2
  Top 0.254: DIN1.1 16.51,6.35 16.51,8.89 R111.P$2
  Top 0.305: R111.P$2 C21.1
N$3
  Top 0.254: DIN2.1 13.97,6.35 13.97,8.89 R112.P$2
  Top 0.305: R112.P$2 C22.1
N$4
  Top 0.254: DIN3.1 11.43,6.35 11.43,8.89 R113.P$2
  Top 0.305: R113.P$2 C23.1
N$5
  Top 0.254: R107.P$1 S1.1 9.65,27.43 U1.24
N$6
  Top 0.254: U1.23 8.89,29.21 S2.1 6.35,26.67 6.35,24.13 R108.P$1
N$7
  Top 0.305: U1.7 21.08,30.99 22.86,29.21 22.86,20.32 R101.P$1
N$8
  Top 0.254: R102.P$2 R103.P$1 R104.P$1 25.4,25.72 23.81,27.3 23.81,29.53 20.57,32.77 U1.8
N$9
  Top 0.254: R104.P$2 R105.P$1 30.48,30.48
  Top 0.305: C3.2 30.48,38.1 30.48,30.48
N$10
  Top 0.305: R106.P$2 29.84,32.38 29.84,36.2 C2.1
N$11
  Top 0.254: 25.4,35.56 C1.2
  Top 0.305: U1.11 C2.2 25.4,35.56
N$12
  Top 0.305: U1.10 22.1,36.32 C1.1 25.4,33.02 R106.P$1 R105.P$2 26.67,26.35 26.67,19.05 R101.P$2
N$13
  Top 1.27: U3.12 91.44,53.34 VR1.1
N$14
  Top 1.27: R3.P$1 R20.P$1 R21.P$2
N$15
  Top 1.27: R4.P$1 R22.P$2 R21.P$1
N$16
  Top 1.27: R5.P$1 R22.P$1 R23.P$2
N$17
  Top 0.254: U8.5 28.57,47.62 64.14,47.62 U7.13
N$18
  Top 1.27: R6.P$1 R24.P$2 R23.P$1
N$19
  Top 1.27: R7.P$1 R24.P$1 R25.P$2
N$20
  Top 1.27: R8.P$1 R26.P$2 R25.P$1
N$21
  Top 1.27: R9.P$1 R26.P$1 R27.P$2
N$22
  Top 1.27: R28.P$2 R27.P$1 R10.P$1
N$23
  Top 1.27: R28.P$1 R29.P$2 R11.P$1
N$24
  Top 1.27: R30.P$2 R29.P$1 R12.P$1
N$25
  Top 1.27: R30.P$1 R31.P$2 R13.P$1
N$26
  Top 1.27: R32.P$2 R31.P$1 R14.P$1
N$27
  Top 1.27: R32.P$1 R33.P$2 R15.P$1
N$28
  Top 1.27: R34.P$2 R33.P$1 R16.P$1
N$29
  Top 1.27: R71.P$2 R70.P$1 R53.P$1
N$30
  Top 1.27: R1.P$1 R2.P$1 R20.P$2
N$31
  Top 1.27: R54.P$1 R72.P$2 R71.P$1
N$32
  Top 1.27: VR1.3 VR1.2 R40.P$2
N$33
  Top 1.27: R40.P$1 R35.P$2
N$34
  Top 1.27: U2.19 R2.P$2
N$35
  Top 1.27: U2.18 R3.P$2
N$36
  Top 1.27: U2.17 R4.P$2
N$37
  Top 1.27: U2.16 R5.P$2
N$38
  Top 1.27: U2.15 R6.P$2
N$39
  Top 1.27: U2.14 R7.P$2
N$40
  Top 1.27: U2.13 R8.P$2
N$41
  Top 1.27: U2.12 R9.P$2
N$42
  Top 1.27: U3.19 R10.P$2
N$43
  Top 1.27: U3.18 R11.P$2
N$44
  Top 1.27: U3.17 R12.P$2
N$45
  Top 1.27: U3.16 R13.P$2
N$46
  Top 1.27: U3.15 R14.P$2
N$47
  Top 1.27: U3.14 R15.P$2
N$48
  Top 1.27: U3.13 R16.P$2
N$49
  Top 1.27: R55.P$1 R72.P$1 R73.P$2
N$50
  Top 1.27: R56.P$1 R74.P$2 R73.P$1
N$51
  Top 1.27: R57.P$1 R74.P$1 R75.P$2
N$52
  Top 1.27: R75.P$1 R76.P$2 R58.P$1
N$53
  Top 1.27: R59.P$1 R76.P$1 R77.P$2
N$54
  Top 1.27: R60.P$1 R77.P$1 R78.P$2
N$55
  Top 1.27: R78.P$1 R79.P$2 R61.P$1
N$56
  Top 1.27: R62.P$1 R79.P$1 R80.P$2
N$57
  Top 1.27: R63.P$1 R81.P$2 R80.P$1
N$58
  Top 1.27: R64.P$1 R81.P$1 R82.P$2
N$59
  Top 1.27: R65.P$1 R83.P$2 R82.P$1
N$60
  Top 1.27: R66.P$1 R83.P$1 R84.P$2
N$61
  Top 1.27: R51.P$1 R52.P$1 R70.P$2
N$62
  Top 1.27: R85.P$2 R90.P$1
N$63
  Top 0.254: U1.6 17.78,29.21 12.7,24.13 C23.2
N$64
  Top 1.27: R52.P$2 U4.12
N$65
  Top 1.27: R53.P$2 U4.13
N$66
  Top 1.27: R54.P$2 U4.14
N$67
  Top 1.27: R55.P$2 U4.15
N$68
  Top 1.27: R56.P$2 U4.16
N$69
  Top 1.27: R57.P$2 U4.17
N$70
  Top 1.27: R90.P$2 VR2.2 VR2.3
N$71
  Top 1.27: R59.P$2 U4.19
N$72
  Top 1.27: R60.P$2 U5.12
N$73
  Top 1.27: R61.P$2 U5.13
N$74
  Top 1.27: R62.P$2 U5.14
N$75
  Top 1.27: R63.P$2 U5.15
N$76
  Top 1.27: R64.P$2 U5.16
N$77
  Top 1.27: R65.P$2 U5.17
N$78
  Top 1.27: R66.P$2 U5.18
N$79
  Top 1.27: U5.19 91.44,15.24 VR2.1
N$80
  Top 0.254: U8.1 12.7,50.8 LRPOL.2
N$81
  Top 0.254: U8.12 19.05,57.15 6.99,57.15 6.35,56.52 6.35,54.61 LRPOL.3
N$82
  Top 0.254: U1.5 18.54,27.43 15.24,24.13 C22.2
N$83
  Top 0.254: U1.4 19.3,25.65 17.78,24.13 C21.2
N$84
  Top 0.254: U1.3 20.07,23.88 19.05,22.86 19.05,19.05 C20.2
N$85  (1 unrouted)
  Bottom 1.27: U3.20 C10.2 68.58,48.26 | 68.58,48.26 43.18,48.26 U2.20 C9.2 38.1,50.8 LPOW2.1 | 68.58,48.26 CC5.P$1
N$86
  Bottom 1.27: 93.98,20.32 C11.2 66.04,20.32 | 93.98,20.32 U5.20 | 66.04,20.32 U4.20 | 93.98,20.32 C12.2 CC7.P$1 | 38.1,20.32 RPOW2.1 | 38.1,20.32 66.04,20.32 | 38.1,20.32 38.1,19.05 CC6.P$1
OUT_L  (via drill 1)
  Top 1.27: R17.P$2 R35.P$1 R34.P$1 97.47,64.77 v104.14,58.42 CC2.P$1
OUT_LL  (via drill 1)
  Top 1.27: v106.68,53.34 CC2.P$2 v104.14,55.88 104.14,53.98 | v106.68,53.34 v106.68,50.8 v106.68,48.26 v106.68,45.72 v106.68,43.18 v106.68,40.64 LOUT.1 | v106.68,53.34 v104.14,53.34
OUT_R  (via drill 1)
  Top 1.27: R67.P$2 R85.P$1 R84.P$1 97.79,3.81 v104.14,10.16 CC3.P$1
OUT_RR  (via drill 1)
  Top 1.27: v106.68,15.24 CC3.P$2 v104.14,12.7 v104.14,15.24 v106.68,15.24 | v106.68,15.24 v106.68,17.78 v106.68,20.32 v106.68,22.86 v106.68,25.4 v106.68,27.94 ROUT.1
SCK
  Top 0.254: U1.22 7.11,30.99 CN1.1

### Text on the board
tPlace: IN | GND
tNames: GND | POW | +5V | DATA | GND | LRCK | BCK | GND | SCK | GND | +5V | L | G | G | R | GND | +5V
